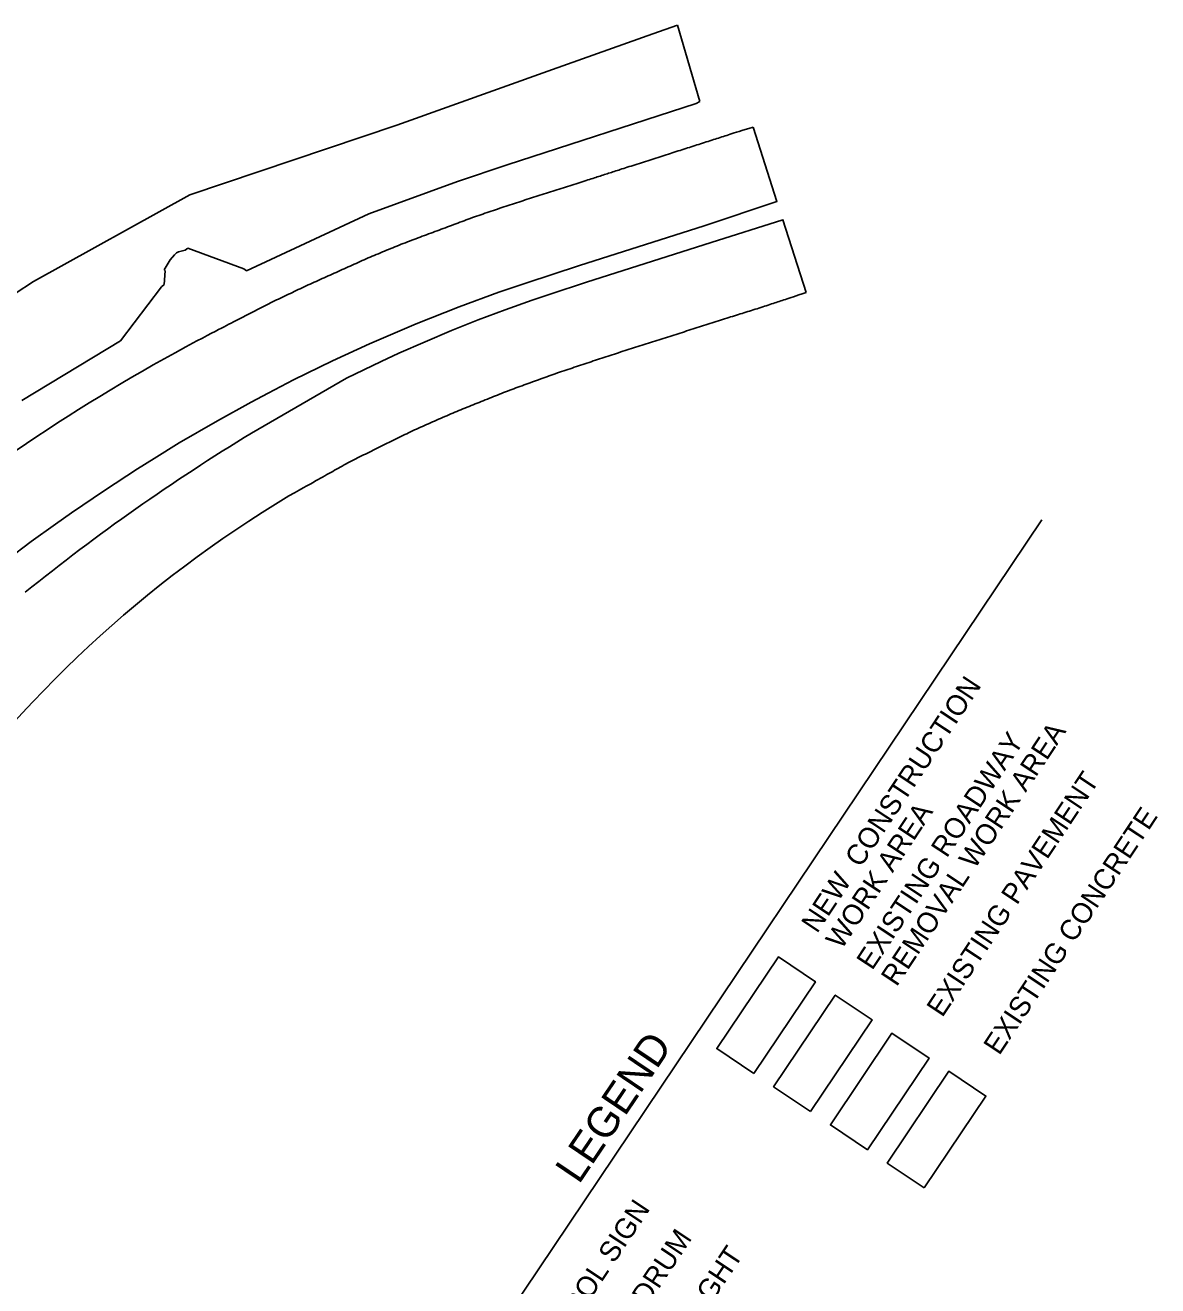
# Model space of a CAD drawing. Extents: x 1795987 to 1799689, y 243690 to 251545.
# Drawn here: x 1798428.4 to 1798861.5, y 250497.4 to 250979.5 of the extents above; entities that cross this region are included whole.
import ezdxf

# ---------------------------------------------------------------- set-up
doc = ezdxf.new("R2010")
doc.units = 0
for name, color, linetype in [('EP', 7, 'Continuous'), ('LEGEND', 7, 'Continuous'), ('Level 2', 7, 'Continuous'), ('Level 62', 7, 'Continuous'), ('Phase 2 Hatching', 7, 'Continuous')]:
    doc.layers.add(name, color=color, linetype=linetype)

msp = doc.modelspace()

# ---------------------------------------------------------------- linework, layer by layer
at = {"layer": 'EP'}
for points in [[(1798715.83, 250911.99), (1798706.71, 250940.52)], [(1798421.6, 250775.14), (1798430.71, 250781.98), (1798439.94, 250788.67), (1798446.15, 250793.04), (1798458.71, 250801.58), (1798471.32, 250809.8), (1798477.69, 250813.81), (1798487.33, 250819.69), (1798501.95, 250828.23), (1798514.78, 250835.33), (1798521.26, 250838.77), (1798531.03, 250843.81), (1798545.85, 250851.06), (1798560.03, 250857.58), (1798567.18, 250860.72), (1798577.96, 250865.27), (1798588.83, 250869.62), (1798594.28, 250871.72), (1798609.55, 250877.31), (1798619.79, 250880.85), (1798640.4, 250887.61), (1798688.08, 250902.78), (1798715.83, 250911.99)], [(1798727, 250877.2), (1798718.12, 250905.04), (1798690.64, 250896.35), (1798643.02, 250881.17), (1798629.12, 250876.63), (1798622.21, 250874.27), (1798611.89, 250870.6), (1798601.64, 250866.75), (1798596.54, 250864.76), (1798591.43, 250862.7), (1798581.28, 250858.44), (1798571.21, 250853.98), (1798564.54, 250850.91), (1798551.3, 250844.54), (1798514.99, 250823.48)]]:
    msp.add_lwpolyline(points, dxfattribs=at)
for centre, radius, start, end in [((1798847.29, 250198.62), 748.7, 118.15094, 129.80104), ((1798929.58, 250141.63), 798, 121.30087, 128.9046), ((1798765.83, 250404.81), 460.1, 120.9411, 144.8621)]:
    msp.add_arc(centre, radius, start, end, dxfattribs=at)
for points in [[(1798706.71, 250940.52), (1798702.17, 250939.08), (1798697.63, 250937.63), (1798693.09, 250936.18), (1798687.38, 250934.36), (1798681.67, 250932.52), (1798675.95, 250930.68), (1798669.6, 250928.65), (1798663.25, 250926.61), (1798656.9, 250924.57), (1798652.58, 250923.18), (1798648.25, 250921.79), (1798643.93, 250920.4), (1798637.43, 250918.31), (1798630.92, 250916.26), (1798624.42, 250914.18), (1798617.93, 250912.1), (1798611.45, 250909.99), (1798605, 250907.8), (1798598.59, 250905.61), (1798592.26, 250903.21), (1798585.91, 250900.84), (1798579.43, 250898.42), (1798572.94, 250896.02), (1798566.54, 250893.37), (1798560.32, 250890.81), (1798554.21, 250888.04), (1798548.08, 250885.29), (1798541.97, 250882.53), (1798535.85, 250879.79), (1798529.8, 250876.91), (1798523.76, 250874.03), (1798517.76, 250871.07), (1798511.83, 250867.99), (1798505.91, 250864.91), (1798499.98, 250861.83), (1798494.06, 250858.75)], [(1798529.27, 250799.44), (1798535.08, 250802.71), (1798540.89, 250805.98), (1798546.7, 250809.25), (1798552.52, 250812.53), (1798558.52, 250815.47), (1798564.5, 250818.45), (1798570.5, 250821.44), (1798576.52, 250824.34), (1798582.64, 250827.07), (1798588.79, 250829.82), (1798594.99, 250832.41), (1798601.24, 250834.92), (1798607.44, 250837.42), (1798613.65, 250839.87), (1798619.93, 250842.16), (1798626.31, 250844.49), (1798632.7, 250846.76), (1798639.15, 250848.9), (1798645.61, 250851.05), (1798652.08, 250853.2), (1798658.57, 250855.27), (1798665.07, 250857.34), (1798671.58, 250859.42), (1798678.08, 250861.49), (1798684.56, 250863.55), (1798691.04, 250865.61), (1798697.52, 250867.68), (1798703.23, 250869.5), (1798708.97, 250871.26), (1798714.67, 250873.14), (1798718.78, 250874.49), (1798722.89, 250875.85), (1798727, 250877.2)]]:
    msp.add_open_spline(points, degree=3, dxfattribs=at)
at = {"layer": 'LEGEND'}
msp.add_line((1798551.69, 250395.05), (1798817.07, 250790.3), dxfattribs=at)
for points in [[(1798706.99, 250578.57), (1798730.56, 250613.67), (1798716.38, 250623.19), (1798692.82, 250588.09)], [(1798728.71, 250563.99), (1798752.28, 250599.09), (1798738.11, 250608.6), (1798714.54, 250573.51)], [(1798750.44, 250549.41), (1798774, 250584.5), (1798759.83, 250594.02), (1798736.26, 250558.92)], [(1798772.16, 250534.82), (1798795.72, 250569.92), (1798781.55, 250579.43), (1798757.99, 250544.34)]]:
    msp.add_lwpolyline(points, close=True, dxfattribs=at)
at = {"layer": 'Level 2'}
msp.add_lwpolyline([(1798772.16, 250534.82), (1798795.72, 250569.92), (1798781.55, 250579.43), (1798757.99, 250544.34)], close=True, dxfattribs=at)
at = {"layer": 'Level 62'}
for p, q in [((1798630, 250962.47), (1798668.45, 250976.22)), ((1798630, 250962.47), (1798668.45, 250976.22)), ((1798668.45, 250976.22), (1798677.83, 250979.45)), ((1798668.45, 250976.22), (1798677.83, 250979.45)), ((1798677.83, 250979.45), (1798686.34, 250950.23)), ((1798677.83, 250979.45), (1798686.34, 250950.23)), ((1798570.52, 250941.2), (1798630, 250962.47)), ((1798570.52, 250941.2), (1798630, 250962.47)), ((1798491.32, 250914.63), (1798570.52, 250941.2)), ((1798491.32, 250914.63), (1798570.52, 250941.2)), ((1798612.69, 250926), (1798593.64, 250919.71)), ((1798612.69, 250926), (1798593.64, 250919.71)), ((1798593.64, 250919.71), (1798559.85, 250907.31)), ((1798593.64, 250919.71), (1798559.85, 250907.31)), ((1798431.57, 250881.49), (1798491.32, 250914.63)), ((1798431.57, 250881.49), (1798491.32, 250914.63)), ((1798559.85, 250907.31), (1798513, 250885.53)), ((1798559.85, 250907.31), (1798513, 250885.53)), ((1798489.61, 250893.48), (1798487.03, 250892.83)), ((1798489.61, 250893.48), (1798487.03, 250892.83)), ((1798490.6, 250894.25), (1798489.61, 250893.48)), ((1798490.6, 250894.25), (1798489.61, 250893.48)), ((1798512, 250886.32), (1798490.6, 250894.25)), ((1798512, 250886.32), (1798490.6, 250894.25)), ((1798513, 250885.53), (1798512, 250886.32)), ((1798513, 250885.53), (1798512, 250886.32)), ((1798399.82, 250860.78), (1798431.57, 250881.49)), ((1798399.82, 250860.78), (1798431.57, 250881.49)), ((1798480.51, 250879.39), (1798464.83, 250858.78)), ((1798480.51, 250879.39), (1798464.83, 250858.78)), ((1798481.52, 250880.29), (1798480.51, 250879.39)), ((1798481.52, 250880.29), (1798480.51, 250879.39)), ((1798464.83, 250858.78), (1798427.17, 250835.94)), ((1798464.83, 250858.78), (1798427.17, 250835.94))]:
    msp.add_line(p, q, dxfattribs=at)
for points in [[(1798686.34, 250950.23), (1798685.01, 250949.46), (1798612.69, 250926)], [(1798686.34, 250950.23), (1798685.01, 250949.46), (1798612.69, 250926)], [(1798688.08, 250902.78), (1798715.83, 250911.99), (1798706.71, 250940.52)], [(1798421.6, 250775.14), (1798430.71, 250781.98), (1798439.94, 250788.67), (1798446.15, 250793.04), (1798458.71, 250801.58), (1798471.32, 250809.8), (1798477.69, 250813.81), (1798487.33, 250819.69), (1798501.95, 250828.23), (1798514.78, 250835.33), (1798521.26, 250838.77), (1798531.03, 250843.81), (1798545.85, 250851.06), (1798560.03, 250857.58), (1798567.18, 250860.72), (1798577.96, 250865.27), (1798588.83, 250869.62), (1798594.28, 250871.72), (1798609.55, 250877.31), (1798619.79, 250880.85), (1798640.4, 250887.61), (1798688.08, 250902.78)], [(1798727, 250877.2), (1798718.12, 250905.04), (1798690.64, 250896.35), (1798643.02, 250881.17), (1798629.12, 250876.63), (1798622.21, 250874.27), (1798611.89, 250870.6), (1798601.64, 250866.75), (1798596.54, 250864.76), (1798591.43, 250862.7), (1798581.28, 250858.44), (1798571.21, 250853.98), (1798564.54, 250850.91), (1798551.3, 250844.54), (1798514.99, 250823.48)], [(1798487.03, 250892.83), (1798486.29, 250892.47), (1798485.52, 250891.59)], [(1798487.03, 250892.83), (1798486.29, 250892.47), (1798485.52, 250891.59)], [(1798485.52, 250891.59), (1798483.88, 250889.72), (1798481.58, 250885.86)], [(1798485.52, 250891.59), (1798483.88, 250889.72), (1798481.58, 250885.86)], [(1798481.58, 250885.86), (1798481.89, 250885.49), (1798481.52, 250880.29)], [(1798481.58, 250885.86), (1798481.89, 250885.49), (1798481.52, 250880.29)], [(1798736.26, 250558.92), (1798750.44, 250549.41), (1798774, 250584.5), (1798759.83, 250594.02), (1798736.26, 250558.92)]]:
    msp.add_lwpolyline(points, dxfattribs=at)
for centre, radius, start, end in [((1798847.29, 250198.62), 748.7, 118.15094, 129.80104), ((1798929.58, 250141.63), 798, 121.30087, 128.9046), ((1798765.83, 250404.81), 460.1, 120.9411, 144.8621)]:
    msp.add_arc(centre, radius, start, end, dxfattribs=at)
for points in [[(1798706.71, 250940.52), (1798702.17, 250939.08), (1798697.63, 250937.63), (1798693.09, 250936.18), (1798687.38, 250934.36), (1798681.67, 250932.52), (1798675.95, 250930.68), (1798669.6, 250928.65), (1798663.25, 250926.61), (1798656.9, 250924.57), (1798652.58, 250923.18), (1798648.25, 250921.79), (1798643.93, 250920.4), (1798637.43, 250918.31), (1798630.92, 250916.26), (1798624.42, 250914.18), (1798617.93, 250912.1), (1798611.45, 250909.99), (1798605, 250907.8), (1798598.59, 250905.61), (1798592.26, 250903.21), (1798585.91, 250900.84), (1798579.43, 250898.42), (1798572.94, 250896.02), (1798566.54, 250893.37), (1798560.32, 250890.81), (1798554.21, 250888.04), (1798548.08, 250885.29), (1798541.97, 250882.53), (1798535.85, 250879.79), (1798529.8, 250876.91), (1798523.76, 250874.03), (1798517.76, 250871.07), (1798511.83, 250867.99), (1798505.91, 250864.91), (1798499.98, 250861.83), (1798494.06, 250858.75)], [(1798529.27, 250799.44), (1798535.08, 250802.71), (1798540.89, 250805.98), (1798546.7, 250809.25), (1798552.52, 250812.53), (1798558.52, 250815.47), (1798564.5, 250818.45), (1798570.5, 250821.44), (1798576.52, 250824.34), (1798582.64, 250827.07), (1798588.79, 250829.82), (1798594.99, 250832.41), (1798601.24, 250834.92), (1798607.44, 250837.42), (1798613.65, 250839.87), (1798619.93, 250842.16), (1798626.31, 250844.49), (1798632.7, 250846.76), (1798639.15, 250848.9), (1798645.61, 250851.05), (1798652.08, 250853.2), (1798658.57, 250855.27), (1798665.07, 250857.34), (1798671.58, 250859.42), (1798678.08, 250861.49), (1798684.56, 250863.55), (1798691.04, 250865.61), (1798697.52, 250867.68), (1798703.23, 250869.5), (1798708.97, 250871.26), (1798714.67, 250873.14), (1798718.78, 250874.49), (1798722.89, 250875.85), (1798727, 250877.2)]]:
    msp.add_open_spline(points, degree=3, dxfattribs=at)
at = {"layer": 'Phase 2 Hatching'}
msp.add_lwpolyline([(1798772.16, 250534.82), (1798795.72, 250569.92), (1798781.55, 250579.43), (1798757.99, 250544.34)], close=True, dxfattribs=at)

# ---------------------------------------------------------------- texts
at = {"layer": 'LEGEND'}
for s, height, rotation, p in [('NEW  CONSTRUCTION', 7.7999, 56.4352, (1798731.16, 250631.88)), ('EXISTING ROADWAY', 7.7999, 56.4352, (1798752.25, 250617.72)), ('REMOVAL WORK AREA', 7.7999, 56.4352, (1798761.62, 250611.5)), ('EXISTING PAVEMENT', 7.7999, 56.4352, (1798779.07, 250599.73)), ('WORK AREA', 7.8, 56.4352, (1798740.52, 250625.66)), ('EXISTING CONCRETE', 7.7999, 56.4352, (1798800.83, 250585.21)), ('LEGEND', 11.7, 55.9561, (1798640.14, 250535.91)), ('TRAFFIC CONTROL SIGN', 7.7999, 56.4352, (1798597.78, 250421.64)), ('CHANNELIZATION DRUM', 7.7999, 56.4352, (1798614.45, 250411.34)), ('TYPE "B" WARNING LIGHT', 7.7999, 56.4352, (1798630.52, 250399.65))]:
    msp.add_text(s, height=height, rotation=rotation, dxfattribs=at).set_placement(p)

doc.saveas('drawing.dxf')
